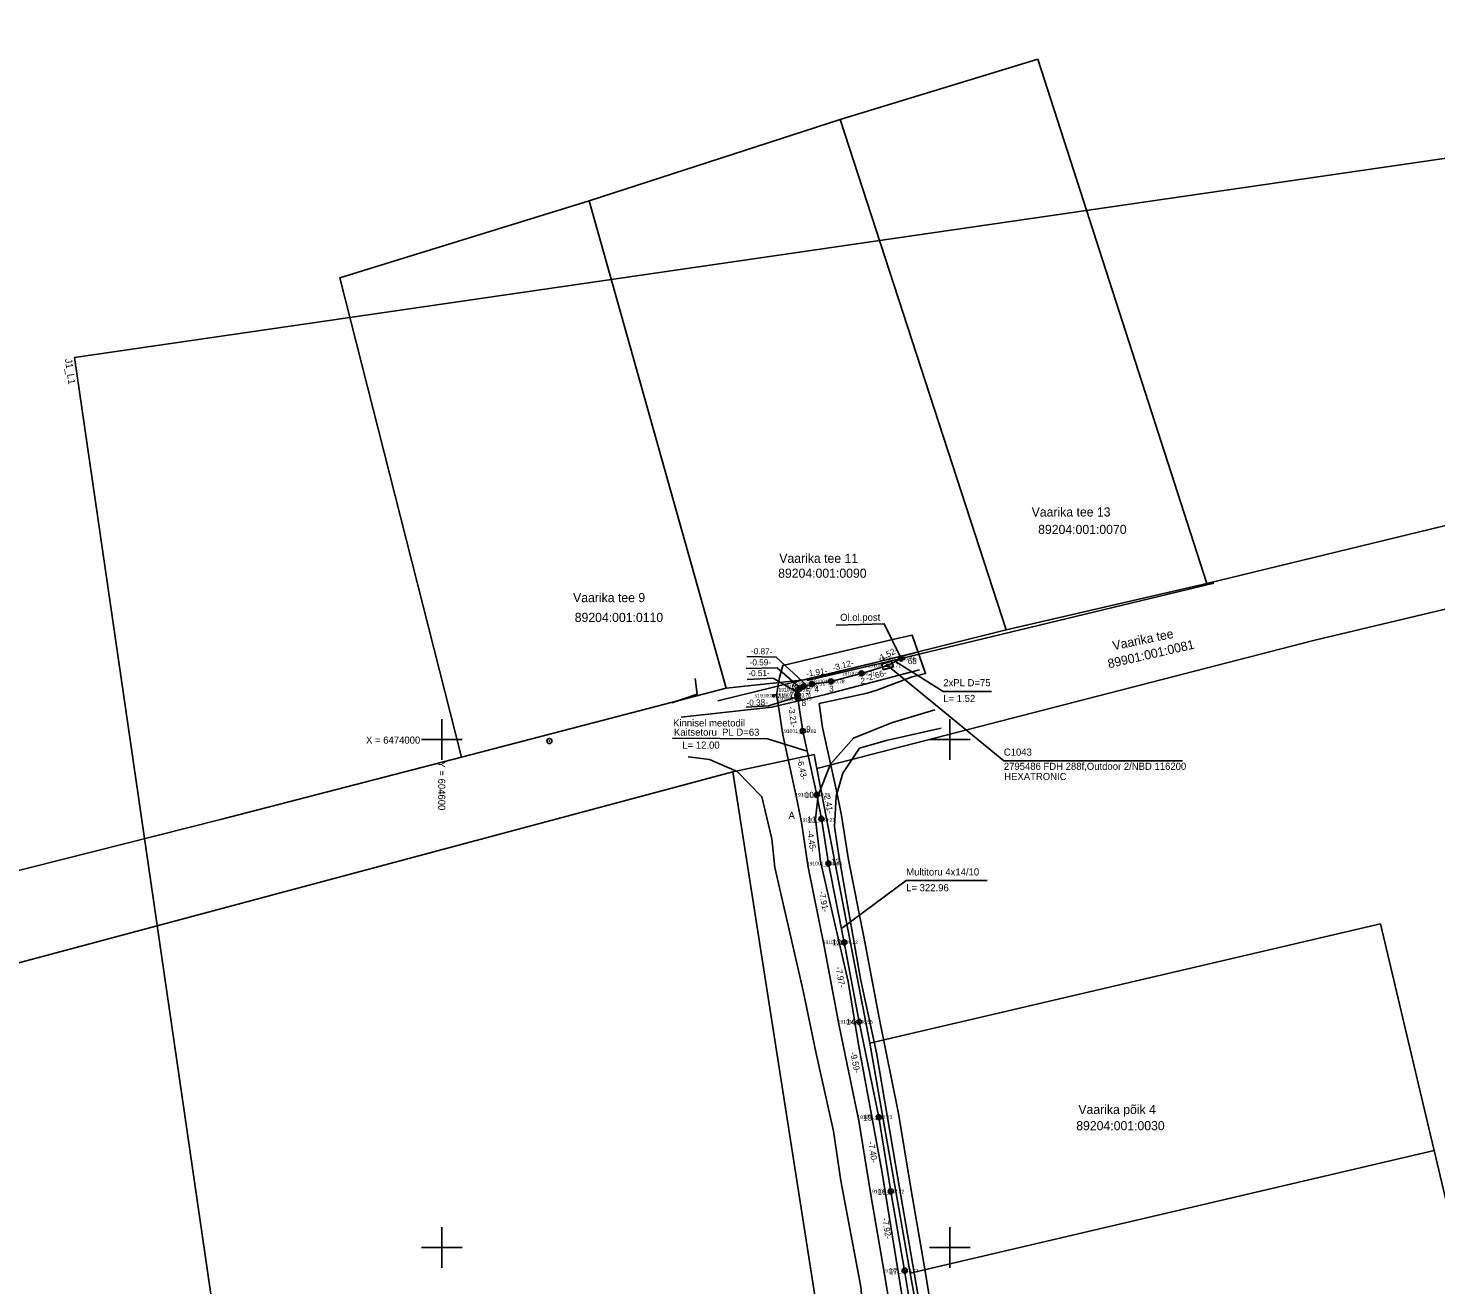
# Model space of a CAD drawing. Extents: x 604066 to 604956, y 6473634 to 6474346.
# Drawn here: x 604559.3 to 604697.8, y 6473946.3 to 6474070 of the extents above; entities that cross this region are included whole.
import ezdxf

# ---------------------------------------------------------------- set-up
doc = ezdxf.new("R2010")
doc.units = 0
for name, color, linetype in [('AED', 7, 'Continuous'), ('JOONSIDE', 7, 'Continuous'), ('KOORDPUNKT', 7, 'Continuous'), ('MOOTKORG', 7, 'Continuous'), ('MOOTMPUNKT', 7, 'Continuous'), ('MOOTNR', 7, 'Continuous'), ('MOOTPIIR', 7, 'Continuous'), ('PIIR', 7, 'Continuous'), ('POST', 7, 'Continuous'), ('SIOHULIIN', 7, 'Continuous'), ('SIRAJATIS', 7, 'Continuous'), ('SITRASS', 7, 'Continuous'), ('TEE', 7, 'Continuous'), ('VORK', 7, 'Continuous'), ('VORMISTUS', 7, 'Continuous')]:
    doc.layers.add(name, color=color, linetype=linetype)

msp = doc.modelspace()

# ---------------------------------------------------------------- linework, layer by layer
at = {"layer": 'AED'}
for points in [[(604627.19, 6474003.81), (604631.05, 6474004.77), (604637.2, 6474006.26), (604646.63, 6474008.54)], [(604624.95, 6474006.02), (604625.13, 6474004.46), (604622.64, 6474003.63)], [(604649.16, 6474001.13), (604643.74, 6473999.92), (604641.11, 6473999.16), (604639.47, 6473996.69), (604638.82, 6473994.42), (604638.66, 6473991.42), (604639.13, 6473988.4), (604641.21, 6473976.45), (604642.8, 6473969.17), (604644.69, 6473957.97), (604647.99, 6473938.75), (604650.86, 6473920.61), (604653.59, 6473905.15), (604655.9, 6473891.46)]]:
    msp.add_lwpolyline(points, dxfattribs=at)
at = {"layer": 'JOONSIDE'}
for points in [[(604635.94, 6474005.32), (604632.93, 6474008.13), (604630.03, 6474008.17)], [(604635.31, 6474005.05), (604633, 6474007.06), (604629.95, 6474007.01)], [(604635.03, 6474004.65), (604632.61, 6474006.04), (604630.07, 6474005.93)], [(604635.02, 6474004.21), (604632.15, 6474003.31), (604629.95, 6474003.2)]]:
    msp.add_lwpolyline(points, dxfattribs=at)
at = {"layer": 'KOORDPUNKT'}
for centre, radius in [((604645.22, 6474007.98), 0.175), ((604645.22, 6474007.98), 0.0175), ((604645.22, 6474007.98), 0.0154), ((604645.22, 6474007.98), 0.00715), ((604645.22, 6474007.98), 0.00922), ((604645.22, 6474007.98), 0.0113), ((604645.22, 6474007.98), 0.0134), ((604645.22, 6474007.98), 0.00508), ((604645.22, 6474007.98), 0.00301), ((604638.3, 6474005.73), 0.25), ((604638.3, 6474005.73), 0.0221), ((604638.3, 6474005.73), 0.025), ((604638.3, 6474005.73), 0.0191), ((604638.3, 6474005.73), 0.0161), ((604641.31, 6474006.51), 0.25), ((604641.31, 6474006.51), 0.0191), ((604641.31, 6474006.51), 0.0221), ((604641.31, 6474006.51), 0.025), ((604641.31, 6474006.51), 0.0102), ((604641.31, 6474006.51), 0.0132), ((604641.31, 6474006.51), 0.0161), ((604641.31, 6474006.51), 0.0043), ((604641.31, 6474006.51), 0.00726), ((604634.99, 6474004.4), 0.25), ((604635.07, 6474004.9), 0.25), ((604634.99, 6474004.4), 0.025), ((604634.99, 6474004.4), 0.0221), ((604634.99, 6474004.4), 0.0161), ((604634.99, 6474004.4), 0.0191), ((604634.99, 6474004.4), 0.0102), ((604634.99, 6474004.4), 0.0132), ((604634.99, 6474004.4), 0.00726), ((604634.99, 6474004.4), 0.0043), ((604635.07, 6474004.9), 0.025), ((604635.07, 6474004.9), 0.0191), ((604635.07, 6474004.9), 0.0221), ((604635.07, 6474004.9), 0.0161), ((604635.07, 6474004.9), 0.00726), ((604635.07, 6474004.9), 0.0102), ((604635.07, 6474004.9), 0.0132), ((604635.07, 6474004.9), 0.0043), ((604635.57, 6474005.22), 0.25), ((604635.57, 6474005.22), 0.025), ((604635.57, 6474005.22), 0.0191), ((604635.57, 6474005.22), 0.0221), ((604635.57, 6474005.22), 0.0161), ((604635.57, 6474005.22), 0.0102), ((604635.57, 6474005.22), 0.0132), ((604635.57, 6474005.22), 0.00726), ((604635.57, 6474005.22), 0.0043), ((604636.41, 6474005.46), 0.25), ((604636.41, 6474005.46), 0.025), ((604636.41, 6474005.46), 0.0161), ((604636.41, 6474005.46), 0.0191), ((604636.41, 6474005.46), 0.0221), ((604636.41, 6474005.46), 0.00726), ((604636.41, 6474005.46), 0.0102), ((604636.41, 6474005.46), 0.0132), ((604636.41, 6474005.46), 0.0043), ((604638.3, 6474005.73), 0.0132), ((604638.3, 6474005.73), 0.0102), ((604638.3, 6474005.73), 0.0043), ((604638.3, 6474005.73), 0.00726), ((604635.06, 6474004.02), 0.25), ((604635.06, 6474004.02), 0.025), ((604635.06, 6474004.02), 0.0161), ((604635.06, 6474004.02), 0.0191), ((604635.06, 6474004.02), 0.0221), ((604635.06, 6474004.02), 0.00726), ((604635.06, 6474004.02), 0.0102), ((604635.06, 6474004.02), 0.0132), ((604635.06, 6474004.02), 0.0043), ((604635.53, 6474000.84), 0.25), ((604635.53, 6474000.84), 0.0221), ((604635.53, 6474000.84), 0.025), ((604635.53, 6474000.84), 0.0161), ((604635.53, 6474000.84), 0.0191), ((604635.53, 6474000.84), 0.0102), ((604635.53, 6474000.84), 0.0132), ((604635.53, 6474000.84), 0.00726), ((604635.53, 6474000.84), 0.0043), ((604636.91, 6473994.56), 0.25), ((604636.91, 6473994.56), 0.0221), ((604636.91, 6473994.56), 0.025), ((604636.91, 6473994.56), 0.0191), ((604636.91, 6473994.56), 0.0102), ((604636.91, 6473994.56), 0.0132), ((604636.91, 6473994.56), 0.0161), ((604636.91, 6473994.56), 0.0043), ((604636.91, 6473994.56), 0.00726), ((604637.37, 6473992.2), 0.25), ((604637.37, 6473992.2), 0.0221), ((604637.37, 6473992.2), 0.025), ((604637.37, 6473992.2), 0.0161), ((604637.37, 6473992.2), 0.0191), ((604637.37, 6473992.2), 0.0102), ((604637.37, 6473992.2), 0.0132), ((604637.37, 6473992.2), 0.00726), ((604637.37, 6473992.2), 0.0043), ((604638.05, 6473987.8), 0.25), ((604638.05, 6473987.8), 0.0221), ((604638.05, 6473987.8), 0.025), ((604638.05, 6473987.8), 0.0191), ((604638.05, 6473987.8), 0.0132), ((604638.05, 6473987.8), 0.0161), ((604638.05, 6473987.8), 0.00726), ((604638.05, 6473987.8), 0.0102), ((604638.05, 6473987.8), 0.0043), ((604639.61, 6473980.04), 0.25), ((604639.61, 6473980.04), 0.025), ((604639.61, 6473980.04), 0.0221), ((604639.61, 6473980.04), 0.0161), ((604639.61, 6473980.04), 0.0191), ((604639.61, 6473980.04), 0.0102), ((604639.61, 6473980.04), 0.0132), ((604639.61, 6473980.04), 0.0043), ((604639.61, 6473980.04), 0.00726), ((604641.08, 6473972.21), 0.25), ((604641.08, 6473972.21), 0.025), ((604641.08, 6473972.21), 0.0161), ((604641.08, 6473972.21), 0.0191), ((604641.08, 6473972.21), 0.0221), ((604641.08, 6473972.21), 0.0132), ((604641.08, 6473972.21), 0.0043), ((604641.08, 6473972.21), 0.00726), ((604641.08, 6473972.21), 0.0102), ((604643.01, 6473962.82), 0.25), ((604643.01, 6473962.82), 0.025), ((604643.01, 6473962.82), 0.0221), ((604643.01, 6473962.82), 0.0161), ((604643.01, 6473962.82), 0.0191), ((604643.01, 6473962.82), 0.0132), ((604643.01, 6473962.82), 0.0043), ((604643.01, 6473962.82), 0.00726), ((604643.01, 6473962.82), 0.0102), ((604644.19, 6473955.52), 0.25), ((604644.19, 6473955.52), 0.0191), ((604644.19, 6473955.52), 0.0221), ((604644.19, 6473955.52), 0.025), ((604644.19, 6473955.52), 0.0161), ((604644.19, 6473955.52), 0.0102), ((604644.19, 6473955.52), 0.0132), ((604644.19, 6473955.52), 0.00726), ((604644.19, 6473955.52), 0.0043), ((604645.56, 6473947.72), 0.25), ((604645.56, 6473947.72), 0.0221), ((604645.56, 6473947.72), 0.025), ((604645.56, 6473947.72), 0.0191), ((604645.56, 6473947.72), 0.0132), ((604645.56, 6473947.72), 0.0161), ((604645.56, 6473947.72), 0.0102), ((604645.56, 6473947.72), 0.0043), ((604645.56, 6473947.72), 0.00726)]:
    msp.add_circle(centre, radius, dxfattribs=at)
at = {"layer": 'MOOTMPUNKT'}
for centre in [(604643.86, 6474007.29), (604645.22, 6474007.98), (604638.3, 6474005.73), (604641.31, 6474006.51), (604632.64, 6474004.32), (604634.99, 6474004.4), (604635.07, 6474004.9), (604635.57, 6474005.22), (604636.41, 6474005.46), (604635.06, 6474004.02), (604635.53, 6474000.84), (604636.91, 6473994.56), (604637.37, 6473992.2), (604638.05, 6473987.8), (604639.61, 6473980.04), (604641.08, 6473972.21), (604643.01, 6473962.82), (604644.19, 6473955.52), (604645.56, 6473947.72)]:
    msp.add_circle(centre, 0.1, dxfattribs=at)
at = {"layer": 'MOOTPIIR'}
msp.add_lwpolyline([(604648.73, 6473940.65), (604647.53, 6473948.05), (604646.16, 6473955.85), (604644.97, 6473963.18), (604643.04, 6473972.6), (604641.58, 6473980.42), (604640.02, 6473988.15), (604639.34, 6473992.54), (604638.86, 6473994.97), (604637.49, 6474001.2), (604637.15, 6474003.55), (604641.86, 6474004.58), (604642.83, 6474004.88), (604646.3, 6474006.18), (604647.62, 6474006.49), (604647.62, 6474006.5), (604646.29, 6474010.29), (604644.53, 6474009.87), (604635.52, 6474007.76), (604633.57, 6474007.3), (604633.24, 6474006.11), (604632.96, 6474004.37), (604633.09, 6474003.69), (604633.56, 6474000.48), (604634.95, 6473994.15), (604635.4, 6473991.85), (604636.08, 6473987.45), (604637.65, 6473979.66), (604639.12, 6473971.83), (604641.04, 6473962.46), (604642.22, 6473955.18), (604643.58, 6473947.38), (604644.78, 6473940.03)], dxfattribs=at)
at = {"layer": 'PIIR'}
for points in [[(604522.44, 6473975.67), (604525.49, 6473978.71), (604556.37, 6473986.61), (604578.23, 6473992.13), (604601.94, 6473998.28), (604628.01, 6474005.05), (604636, 6474005.92), (604655.56, 6474010.79), (604675.3, 6474015.38), (604693.95, 6474019.91), (604713.95, 6474024.76), (604740.99, 6474031.56), (604856.37, 6474070.04), (604842.6, 6474053.11), (604799.53, 6474039.98), (604795.34, 6474038.79), (604791.09, 6474037.83), (604742.9, 6474023.35), (604685.8, 6474009.75), (604636.91, 6473997.15), (604636.64, 6473998.53), (604628.65, 6473996.82), (604524, 6473968.82)], [(604658.67, 6474066.98), (604675.3, 6474015.38), (604655.56, 6474010.79), (604639.22, 6474061.04)], [(604639.22, 6474061.04), (604655.56, 6474010.79), (604636, 6474005.92), (604628.01, 6474005.05), (604614.52, 6474053.04)], [(604614.52, 6474053.04), (604628.01, 6474005.05), (604601.94, 6473998.28), (604589.96, 6474045.47)], [(604645.55, 6473867.92), (604639.6, 6473926.84), (604628.65, 6473996.82), (604636.64, 6473998.53), (604636.91, 6473997.15), (604642.13, 6473970.12), (604646.1, 6473947.47), (604649.97, 6473926.14), (604659, 6473875.69)], [(604524, 6473968.82), (604628.65, 6473996.82), (604639.6, 6473926.84), (604645.55, 6473867.92), (604575.16, 6473852.02), (604549.55, 6473854.82)], [(604692.4, 6473981.86), (604697.15, 6473961.76), (604697.68, 6473959.53), (604646.1, 6473947.47), (604642.13, 6473970.12)], [(604697.68, 6473959.53), (604702.56, 6473938.89), (604702.74, 6473938.11), (604649.97, 6473926.14), (604646.1, 6473947.47)]]:
    msp.add_lwpolyline(points, close=True, dxfattribs=at)
at = {"layer": 'POST'}
msp.add_lwpolyline([(604645.22, 6474007.98), (604643.56, 6474011.41), (604638.83, 6474011.26)], dxfattribs=at)
for centre, radius in [((604645.22, 6474007.98), 0.25), ((604645.22, 6474007.98), 0.0234), ((604610.6, 6473999.86), 0.25), ((604610.6, 6473999.86), 0.0234)]:
    msp.add_circle(centre, radius, dxfattribs=at)
at = {"layer": 'SIOHULIIN'}
for q in [(604675.99, 6474015.39), (604635.97, 6474005.81)]:
    msp.add_line((604645.22, 6474007.98), q, dxfattribs=at)
at = {"layer": 'SIRAJATIS'}
msp.add_lwpolyline([(604643.3, 6474007.44), (604644.26, 6474007.72), (604644.42, 6474007.14), (604643.46, 6474006.87)], close=True, dxfattribs=at)
msp.add_lwpolyline([(604643.86, 6474007.29), (604655.32, 6473997.92), (604672.92, 6473997.92)], dxfattribs=at)
for centre, radius in [((604643.67, 6474007.24), 0.0304), ((604643.67, 6474007.24), 0.029), ((604643.67, 6474007.24), 0.0277), ((604643.67, 6474007.24), 0.0263), ((604643.67, 6474007.24), 0.0249), ((604643.67, 6474007.24), 0.0236), ((604643.67, 6474007.24), 0.0222), ((604643.67, 6474007.24), 0.0209), ((604643.67, 6474007.24), 0.0195), ((604643.67, 6474007.24), 0.0181), ((604643.67, 6474007.24), 0.0168), ((604643.67, 6474007.24), 0.0154), ((604643.67, 6474007.24), 0.014), ((604643.67, 6474007.24), 0.0127), ((604643.67, 6474007.24), 0.0113), ((604643.67, 6474007.24), 0.00996), ((604643.67, 6474007.24), 0.0086), ((604643.67, 6474007.24), 0.00724), ((604643.67, 6474007.24), 0.00587), ((604643.67, 6474007.24), 0.00451), ((604643.67, 6474007.24), 0.00315), ((604643.67, 6474007.24), 0.00179), ((604643.67, 6474007.24), 0.000426), ((604644.05, 6474007.35), 0.0304), ((604644.05, 6474007.35), 0.029), ((604644.05, 6474007.35), 0.0277), ((604644.05, 6474007.35), 0.0263), ((604644.05, 6474007.35), 0.0249), ((604644.05, 6474007.35), 0.0236), ((604644.05, 6474007.35), 0.0222), ((604644.05, 6474007.35), 0.0209), ((604644.05, 6474007.35), 0.0195), ((604644.05, 6474007.35), 0.0181), ((604644.05, 6474007.35), 0.0168), ((604644.05, 6474007.35), 0.0154), ((604644.05, 6474007.35), 0.014), ((604644.05, 6474007.35), 0.0127), ((604644.05, 6474007.35), 0.0113), ((604644.05, 6474007.35), 0.00996), ((604644.05, 6474007.35), 0.0086), ((604644.05, 6474007.35), 0.00724), ((604644.05, 6474007.35), 0.00587), ((604644.05, 6474007.35), 0.00451), ((604644.05, 6474007.35), 0.00315), ((604644.05, 6474007.35), 0.00179), ((604644.05, 6474007.35), 0.000426)]:
    msp.add_circle(centre, radius, dxfattribs=at)
at = {"layer": 'SITRASS'}
msp.add_line((604643.86, 6474007.29), (604645.22, 6474007.98), dxfattribs=at)
for points in [[(604643.86, 6474007.29), (604641.31, 6474006.51), (604638.3, 6474005.73), (604636.41, 6474005.46), (604635.57, 6474005.22), (604635.07, 6474004.9), (604634.99, 6474004.4), (604635.06, 6474004.02), (604635.53, 6474000.84), (604636.91, 6473994.56), (604637.37, 6473992.2), (604638.05, 6473987.8), (604639.61, 6473980.04), (604641.08, 6473972.21), (604643.01, 6473962.82), (604644.19, 6473955.52), (604645.56, 6473947.72), (604646.76, 6473940.34)], [(604644.67, 6474007.7), (604649.36, 6474004.75), (604654.12, 6474004.75)], [(604637.37, 6473992.2), (604636.91, 6473994.56), (604635.53, 6474000.84), (604635.06, 6474004.02)], [(604635.96, 6473998.85), (604632.07, 6474000.09), (604622.71, 6474000.15)], [(604639.34, 6473981.4), (604645.71, 6473986.12), (604653.69, 6473986.12)]]:
    msp.add_lwpolyline(points, dxfattribs=at)
at = {"layer": 'TEE'}
for points in [[(604623.57, 6474002.22), (604632.5, 6474003.19), (604637.76, 6474004.44), (604647.01, 6474006.87)], [(604648.52, 6474002.92), (604644.27, 6474001.65), (604640.52, 6474000.14), (604638.25, 6473997.57), (604637.05, 6473994.53), (604636.78, 6473992.15), (604637.27, 6473988), (604640, 6473976.17), (604641.01, 6473969.99), (604643.32, 6473957.55), (604646.5, 6473937.87), (604647.73, 6473925.79), (604648.09, 6473919.8), (604648.79, 6473904.83), (604649.3, 6473896), (604649.61, 6473889), (604649.96, 6473884.59), (604650.62, 6473874.9), (604651.53, 6473867.46), (604652.99, 6473857.52), (604655.83, 6473843.7), (604658.81, 6473832.59), (604663.41, 6473815.74)], [(604624.27, 6473998.3), (604626.35, 6473998.03), (604629.09, 6473996.87), (604631.51, 6473994.38), (604632.49, 6473990.22), (604632.77, 6473987.41), (604635.58, 6473975.26), (604636.85, 6473969.11), (604638.56, 6473961.45), (604639.29, 6473956.57), (604641.25, 6473946.14), (604641.68, 6473941.22), (604644.02, 6473919.05), (604644.07, 6473913.61), (604644.8, 6473904.28), (604645.26, 6473896.15), (604645.91, 6473880.5), (604645.92, 6473874.95), (604646.44, 6473871.29), (604646.95, 6473866.69), (604648.67, 6473857.5), (604651.95, 6473842.63), (604654.6, 6473831.66), (604658.7, 6473815.39)]]:
    msp.add_lwpolyline(points, dxfattribs=at)
at = {"layer": 'VORK'}
for p, q in [((604600, 6474002), (604600, 6473998)), ((604650, 6474002), (604650, 6473998)), ((604598, 6474000), (604602, 6474000)), ((604648, 6474000), (604652, 6474000)), ((604600, 6473952), (604600, 6473948)), ((604650, 6473952), (604650, 6473948)), ((604598, 6473950), (604602, 6473950)), ((604648, 6473950), (604652, 6473950))]:
    msp.add_line(p, q, dxfattribs=at)
at = {"layer": 'VORMISTUS'}
msp.add_lwpolyline([(604563.86, 6474037.6), (604705.86, 6474058.26), (604764.62, 6473654.52), (604622.61, 6473633.85)], close=True, dxfattribs=at)

# ---------------------------------------------------------------- texts
at = {"layer": 'JOONSIDE'}
for s, rotation, p in [('-0.87-', 358.2757, (604630.43, 6474008.42)), ('-1.52-', 26.7269, (604643.08, 6474007.66)), ('-0.59-', 0.0243, (604630.31, 6474007.3)), ('-3.12-', 14.5002, (604638.56, 6474006.77)), ('-0.51-', 0.2678, (604630.18, 6474006.24)), ('-1.91-', 7.994, (604635.9, 6474006.19)), ('-2.66-', 17.1681, (604641.84, 6474005.73)), ('-0.38-', 1.7581, (604630.01, 6474003.32)), ('-3.21-', 278.3343, (604634.11, 6474003.22)), ('-6.43-', 282.3897, (604634.96, 6473998.05)), ('-2.41-', 281.1549, (604637.57, 6473994.72)), ('-4.45-', 278.731, (604635.95, 6473991)), ('-7.91-', 281.4349, (604637.1, 6473985.03)), ('-7.97-', 280.5834, (604638.75, 6473977.59)), ('-9.59-', 281.603, (604640.2, 6473969.18)), ('-7.40-', 279.2141, (604641.97, 6473960.38)), ('-7.92-', 279.9275, (604643.33, 6473952.85))]:
    msp.add_text(s, height=0.6, rotation=rotation, dxfattribs=at).set_placement(p)
at = {"layer": 'KOORDPUNKT'}
for s, p in [('68 ', (604645.87, 6474007.43)), ('2 ', (604641.21, 6474005.49)), ('7 ', (604634.22, 6474004.09)), ('6 ', (604634.42, 6474004.92)), ('5 ', (604635.82, 6474004.46)), ('4 ', (604636.7, 6474004.66)), ('3 ', (604638.13, 6474004.71)), ('8 ', (604635.41, 6474003.31)), ('9 ', (604635.87, 6474000.75)), ('10 ', (604635.72, 6473994.26)), ('11 ', (604635.98, 6473991.83)), ('12 ', (604638.3, 6473987.67)), ('13 ', (604638.42, 6473979.74)), ('14 ', (604639.82, 6473971.92)), ('15 ', (604641.46, 6473962.49)), ('16 ', (604642.89, 6473955.18)), ('17 ', (604643.99, 6473947.37))]:
    msp.add_text(s, height=0.6, dxfattribs=at).set_placement(p)
at = {"layer": 'MOOTKORG'}
for s, p in [(' 50.71', (604643.86, 6474007.12)), (' 50.74', (604645.22, 6474007.8)), (' 50.78', (604638.3, 6474005.55)), (' 50.71', (604641.31, 6474006.33)), (' 52.53', (604632.64, 6474004.15)), (' 50.78', (604634.99, 6474004.22)), (' 50.77', (604635.07, 6474004.73)), (' 50.76', (604635.57, 6474005.04)), (' 50.76', (604636.41, 6474005.29)), (' 50.79', (604635.06, 6474003.84)), (' 50.82', (604635.53, 6474000.66)), (' 50.39', (604636.91, 6473994.38)), (' 50.21', (604637.39, 6473991.92)), (' 49.90', (604638.05, 6473987.62)), (' 49.22', (604639.61, 6473979.87)), (' 48.55', (604641.08, 6473972.04)), (' 47.73', (604643.01, 6473962.65)), (' 47.22', (604644.19, 6473955.34)), (' 46.72', (604645.56, 6473947.54))]:
    msp.add_text(s, height=0.35, dxfattribs=at).set_placement(p)
at = {"layer": 'MOOTNR'}
for s, p in [('191001_2 ', (604641.93, 6474007.12)), ('191001_36 ', (604643.05, 6474007.8)), ('191001_6 ', (604636.37, 6474005.55)), ('191001_5 ', (604639.39, 6474006.33)), ('s1910011 ', (604630.82, 6474004.15)), ('191001_10 ', (604632.89, 6474004.22)), ('191001_9 ', (604633.15, 6474004.73)), ('191001_8 ', (604633.65, 6474005.04)), ('191001_7 ', (604634.49, 6474005.29)), ('191001_11 ', (604633.03, 6474003.84)), ('191001_12 ', (604633.43, 6474000.66)), ('191001_13 ', (604634.81, 6473994.38)), ('191001_14 ', (604635.26, 6473991.92)), ('191001_15 ', (604635.95, 6473987.62)), ('191001_16 ', (604637.52, 6473979.87)), ('191001_17 ', (604638.98, 6473972.04)), ('191001_18 ', (604640.91, 6473962.65)), ('191001_19 ', (604642.09, 6473955.34)), ('191001_20 ', (604643.39, 6473947.54))]:
    msp.add_text(s, height=0.35, dxfattribs=at).set_placement(p)
at = {"layer": 'PIIR'}
for s, p in [('Vaarika tee 13', (604658.06, 6474021.96)), ('89204:001:0070', (604658.7, 6474020.24)), ('Vaarika tee 11', (604633.22, 6474017.4)), ('89204:001:0090', (604633.11, 6474015.93)), ('Vaarika tee 9', (604612.93, 6474013.53)), ('89204:001:0110', (604613.09, 6474011.58)), ('Vaarika põik 4', (604662.66, 6473963.14)), ('89204:001:0030', (604662.45, 6473961.54))]:
    msp.add_text(s, height=0.9, dxfattribs=at).set_placement(p)
for s, rotation, p in [('Vaarika tee', 11.7062, (604666.12, 6474008.79)), ('89901:001:0081', 13.0396, (604665.66, 6474007.01))]:
    msp.add_text(s, height=0.9, rotation=rotation, dxfattribs=at).set_placement(p)
at = {"layer": 'POST'}
msp.add_text('Ol.ol.post', height=0.7, dxfattribs=at).set_placement((604639.21, 6474011.69))
at = {"layer": 'SIRAJATIS'}
for s, p in [('C1043', (604655.32, 6473998.42)), ('2795486 FDH 288f,Outdoor 2/NBD 116200', (604655.32, 6473997.02)), ('HEXATRONIC', (604655.36, 6473996.02))]:
    msp.add_text(s, height=0.7, dxfattribs=at).set_placement(p)
at = {"layer": 'SITRASS'}
for s, p in [('2xPL D=75 ', (604649.36, 6474005.25)), ('L= 1.52', (604649.36, 6474003.7)), ('Kinnisel meetodil', (604622.77, 6474001.29)), ('Kaitsetoru  PL D=63', (604622.86, 6474000.38)), ('L= 12.00', (604623.68, 6473999.11)), ('Multitoru 4x14/10 ', (604645.71, 6473986.62)), ('L= 322.96', (604645.71, 6473985.07))]:
    msp.add_text(s, height=0.7, dxfattribs=at).set_placement(p)
at = {"layer": 'TEE'}
msp.add_text('A', height=0.7, dxfattribs=at).set_placement((604634.13, 6473992.19))
at = {"layer": 'VORK'}
msp.add_text('X = 6474000', height=0.7, dxfattribs=at).set_placement((604592.55, 6473999.6))
msp.add_text('Y = 604600 ', height=0.7, rotation=270, dxfattribs=at).set_placement((604599.65, 6473997.85))
at = {"layer": 'VORMISTUS'}
msp.add_text('J1_L1', height=0.7, rotation=278.2799, dxfattribs=at).set_placement((604562.91, 6474037.46))

doc.saveas('drawing.dxf')
